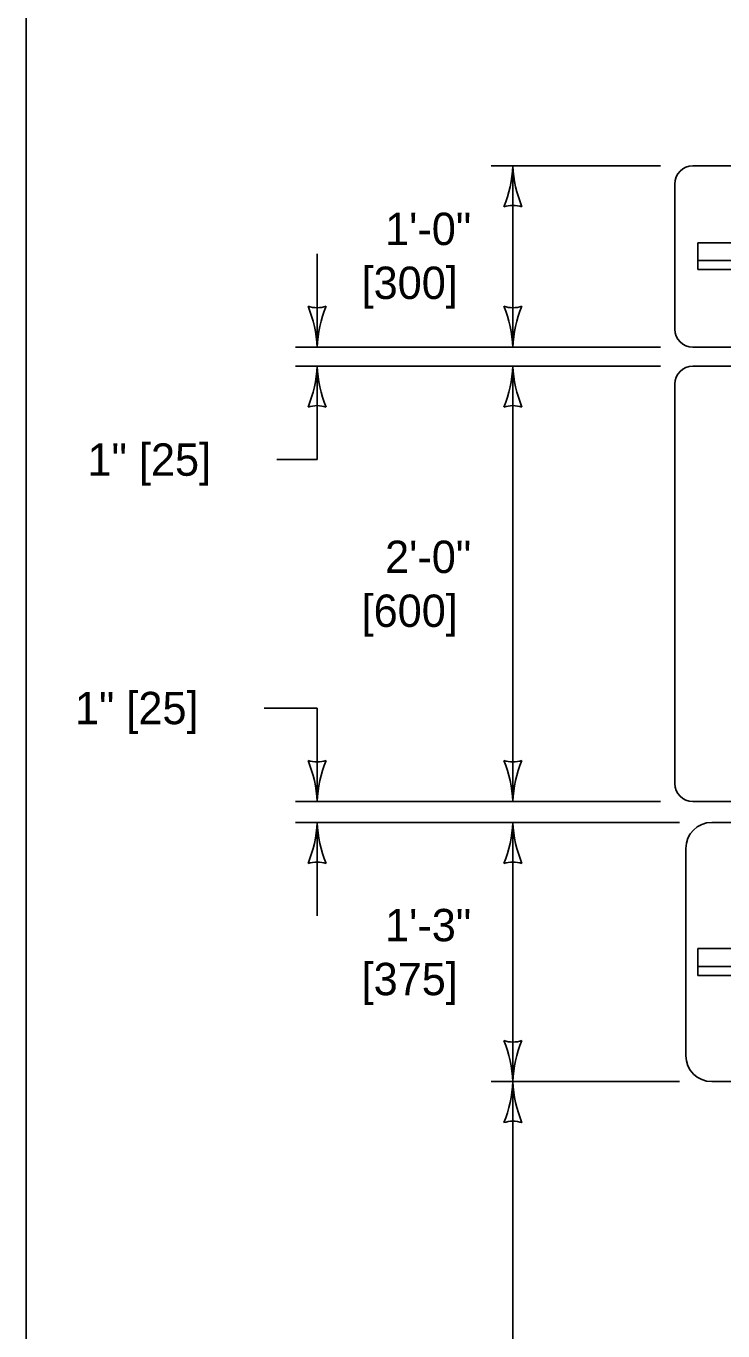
# Model space of a CAD drawing. Extents: x 49991.4 to 50021, y 49987.6 to 50011.4.
# Drawn here: x 49999.384 to 50000.676, y 49989.927 to 49992.347 of the extents above; entities that cross this region are included whole.
import ezdxf

# ---------------------------------------------------------------- set-up
doc = ezdxf.new("R2010")
doc.units = 0
for name, color, linetype in [('Level 1', 7, 'Continuous'), ('Level 2', 7, 'Continuous'), ('Level 3', 7, 'Continuous'), ('Level 4', 7, 'Continuous')]:
    doc.layers.add(name, color=color, linetype=linetype)

msp = doc.modelspace()

# ---------------------------------------------------------------- linework, layer by layer
at = {"layer": 'Level 1'}
msp.add_lwpolyline([(49999.3835, 49998.9992), (50016.7501, 49998.9992), (50016.7501, 49987.7988), (49999.3835, 49987.7988)], close=True, dxfattribs=at)
at = {"layer": 'Level 3'}
for p, q in [((50000.2463, 49992.0873), (50000.5601, 49992.0873)), ((50000.2863, 49991.7509), (50000.2863, 49992.0873)), ((49999.9233, 49991.7509), (49999.9233, 49991.9243)), ((49999.8833, 49991.7509), (50000.5602, 49991.7509)), ((49999.8833, 49991.7161), (50000.5602, 49991.7161)), ((49999.9233, 49991.5427), (49999.9233, 49991.7161)), ((50000.2863, 49990.9086), (50000.2863, 49991.7161)), ((49999.8485, 49991.5427), (49999.9233, 49991.5427)), ((49999.8252, 49991.082), (49999.9233, 49991.082)), ((49999.9233, 49990.9086), (49999.9233, 49991.082)), ((49999.8833, 49990.9086), (50000.5602, 49990.9086)), ((49999.8833, 49990.8698), (50000.5953, 49990.8698)), ((49999.9233, 49990.6964), (49999.9233, 49990.8698)), ((50000.2863, 49990.3892), (50000.2863, 49990.8698)), ((50000.2463, 49990.3892), (50000.5953, 49990.3892)), ((50000.2863, 49988.4948), (50000.2863, 49990.3892))]:
    msp.add_line(p, q, dxfattribs=at)
for centre, radius, start, end in [((50000.0642, 49992.0965), 0.2223, 337.456, 357.6395), ((50000.519, 49992.0988), 0.233, 182.8273, 202.0772), ((50000.2863, 49991.9591), 0.0548, 72.1388, 107.8612), ((49999.9233, 49991.8791), 0.0548, 252.1388, 287.8612), ((49999.6906, 49991.7394), 0.233, 2.8273, 22.0772), ((50000.1454, 49991.7417), 0.2223, 157.456, 177.6395), ((50000.2863, 49991.8791), 0.0548, 252.1388, 287.8612), ((50000.0536, 49991.7394), 0.233, 2.8273, 22.0772), ((50000.5084, 49991.7417), 0.2223, 157.456, 177.6395), ((49999.7011, 49991.7253), 0.2223, 337.456, 357.6395), ((50000.156, 49991.7276), 0.233, 182.8273, 202.0772), ((50000.0642, 49991.7253), 0.2223, 337.456, 357.6395), ((50000.519, 49991.7276), 0.233, 182.8273, 202.0772), ((49999.9233, 49991.5879), 0.0548, 72.1388, 107.8612), ((50000.2863, 49991.5879), 0.0548, 72.1388, 107.8612), ((49999.9233, 49991.0368), 0.0548, 252.1388, 287.8612), ((49999.6906, 49990.8971), 0.233, 2.8273, 22.0772), ((50000.1454, 49990.8994), 0.2223, 157.456, 177.6395), ((50000.2863, 49991.0368), 0.0548, 252.1388, 287.8612), ((50000.0536, 49990.8971), 0.233, 2.8273, 22.0772), ((50000.5084, 49990.8994), 0.2223, 157.456, 177.6395), ((49999.7011, 49990.879), 0.2223, 337.456, 357.6395), ((50000.156, 49990.8813), 0.233, 182.8273, 202.0772), ((50000.0642, 49990.879), 0.2223, 337.456, 357.6395), ((50000.519, 49990.8813), 0.233, 182.8273, 202.0772), ((49999.9233, 49990.7416), 0.0548, 72.1388, 107.8612), ((50000.2863, 49990.7416), 0.0548, 72.1388, 107.8612), ((50000.2863, 49990.5174), 0.0548, 252.1388, 287.8612), ((50000.0536, 49990.3777), 0.233, 2.8273, 22.0772), ((50000.5084, 49990.38), 0.2223, 157.456, 177.6395), ((50000.0642, 49990.3984), 0.2223, 337.456, 357.6395), ((50000.519, 49990.4007), 0.233, 182.8273, 202.0772), ((50000.2863, 49990.261), 0.0548, 72.1388, 107.8612)]:
    msp.add_arc(centre, radius, start, end, dxfattribs=at)
at = {"layer": 'Level 4'}
for p, q in [((50000.6202, 49992.0873), (50000.7307, 49992.0873)), ((50000.5865, 49991.7845), (50000.5866, 49992.0537)), ((50000.6291, 49991.9449), (50000.7664, 49991.9449)), ((50000.6291, 49991.895), (50000.6291, 49991.9449)), ((50000.6291, 49991.9117), (50000.7664, 49991.9117)), ((50000.6291, 49991.895), (50000.7664, 49991.895)), ((50000.6201, 49991.7509), (50000.7307, 49991.7509)), ((50000.6202, 49991.7161), (50000.731, 49991.7161)), ((50000.5866, 49991.6825), (50000.5866, 49990.9422)), ((50000.6202, 49990.9086), (50000.731, 49990.9086)), ((50000.6553, 49990.8698), (50000.7786, 49990.8698)), ((50000.6072, 49990.4373), (50000.6072, 49990.8218)), ((50000.6291, 49990.6361), (50000.6291, 49990.5861)), ((50000.6291, 49990.6361), (50000.7624, 49990.6361)), ((50000.6291, 49990.6029), (50000.7624, 49990.6029)), ((50000.6291, 49990.5861), (50000.7624, 49990.5861)), ((50000.6553, 49990.3892), (50000.7786, 49990.3892))]:
    msp.add_line(p, q, dxfattribs=at)
for centre, radius, start, end in [((50000.6202, 49992.0537), 0.0336, 90, 180), ((50000.6201, 49991.7845), 0.0336, 180, 270), ((50000.6202, 49991.6825), 0.0336, 90, 180), ((50000.6202, 49990.9422), 0.0336, 180, 270), ((50000.6553, 49990.8218), 0.0481, 90, 180), ((50000.6553, 49990.4373), 0.0481, 180, 270)]:
    msp.add_arc(centre, radius, start, end, dxfattribs=at)

# ---------------------------------------------------------------- texts
at = {"layer": 'Level 2'}
for s, p in [('1\'-0"', (50000.0493, 49991.9405)), ('[300]', (50000.0058, 49991.8405)), ('1" [25]', (49999.4974, 49991.5127)), ('2\'-0"', (50000.0493, 49991.3324)), ('[600]', (50000.0058, 49991.2324)), ('1" [25]', (49999.4741, 49991.052)), ('1\'-3"', (50000.0493, 49990.6495)), ('[375]', (50000.0058, 49990.5495))]:
    msp.add_text(s, height=0.06, dxfattribs=at).set_placement(p)

doc.saveas('drawing.dxf')
